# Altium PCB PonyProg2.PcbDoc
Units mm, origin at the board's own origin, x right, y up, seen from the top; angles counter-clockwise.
Board outline 221.9 x 83.4 mm, 2 copper layers (Top Layer, Bottom Layer); 90 components, 71 nets, 512 pads, 0 vias.
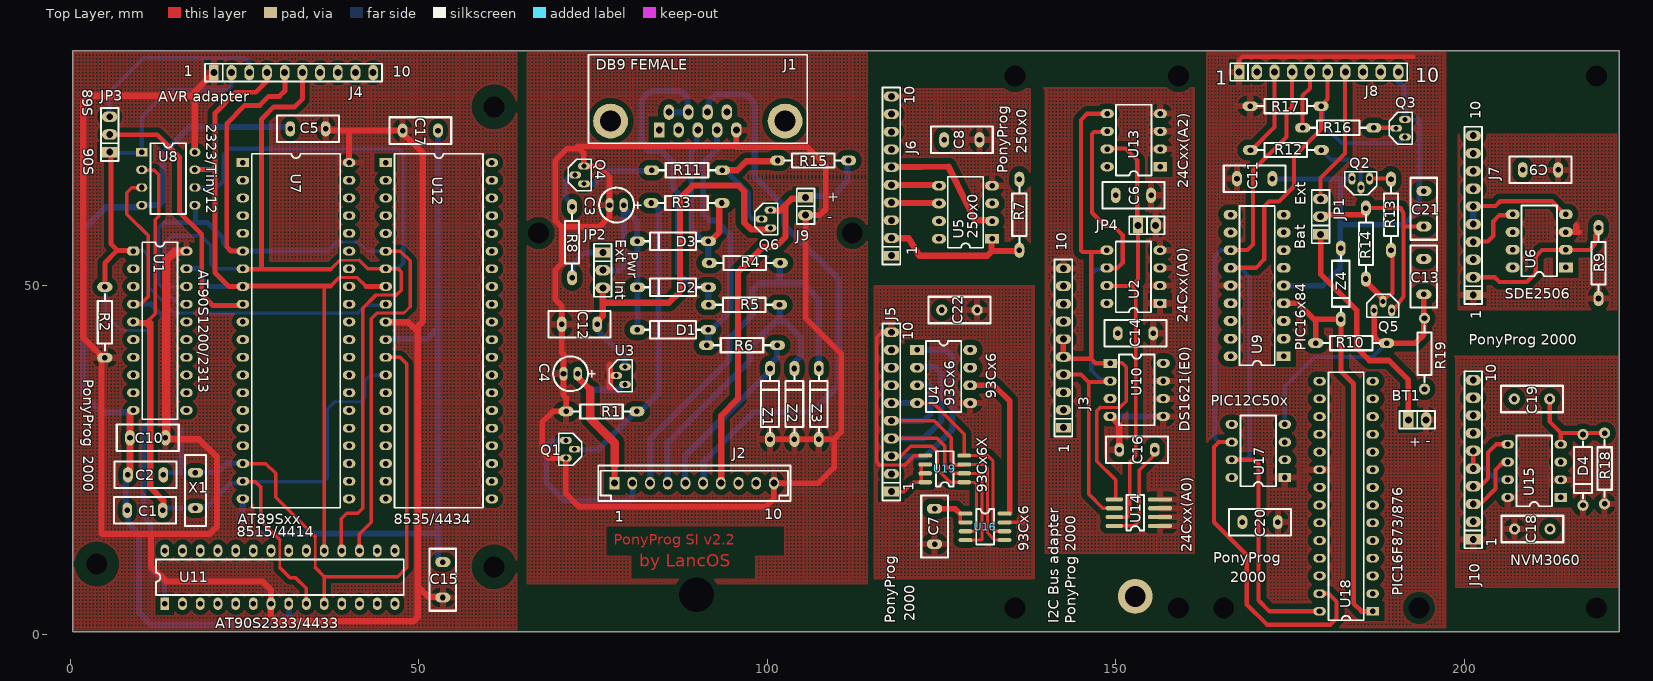
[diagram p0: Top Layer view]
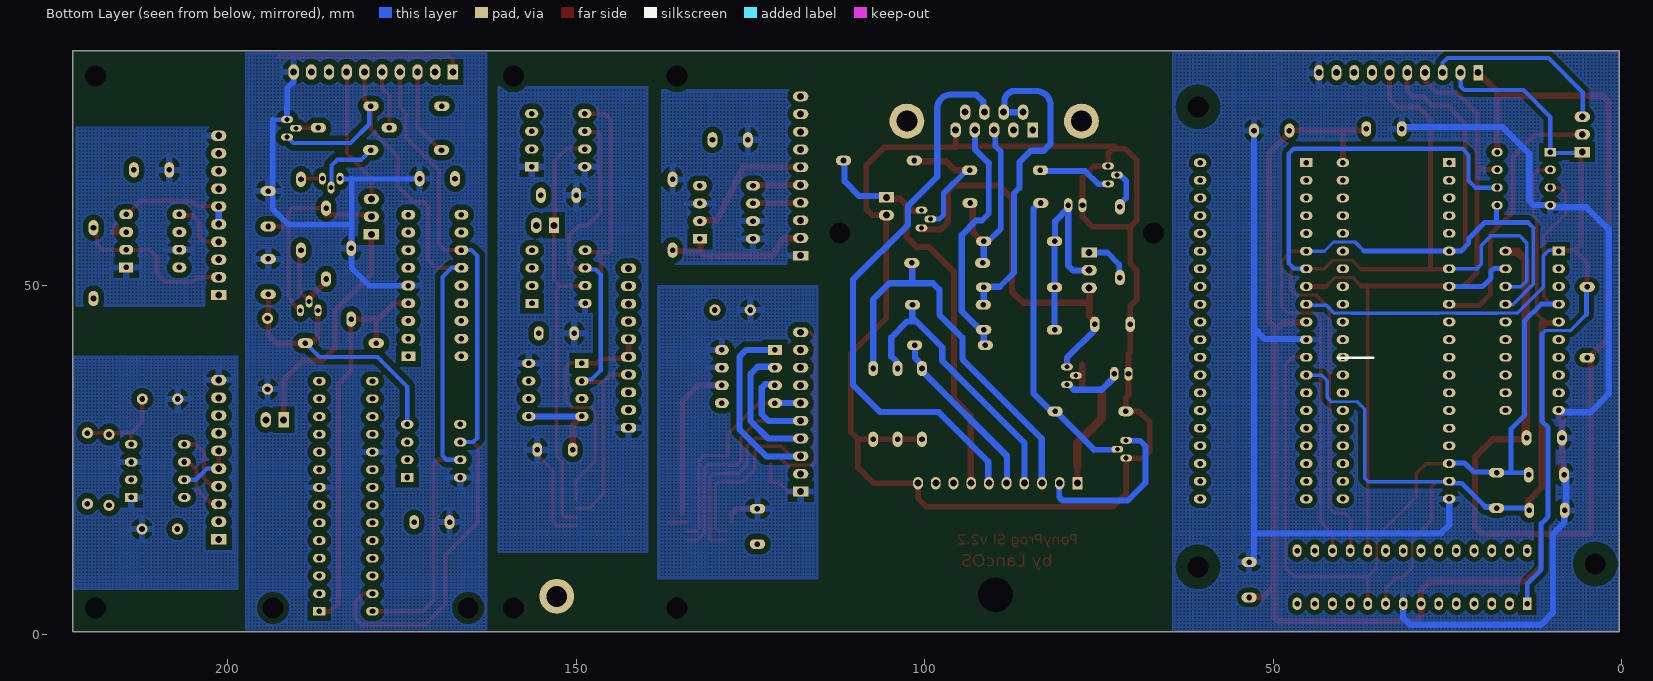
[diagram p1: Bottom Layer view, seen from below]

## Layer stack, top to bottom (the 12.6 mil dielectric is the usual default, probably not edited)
Top Solder: solder mask 0.0102, Solder Resist, Dk 3.5
Top Layer: signal copper 0.0356
Dielectric 1: dielectric 0.32, FR-4, Dk 4.8
Bottom Layer: signal copper 0.0356
Bottom Solder: solder mask 0.0102, Solder Resist, Dk 3.5

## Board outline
0.35,0.35 222.25,0.35 222.25,83.75 0.35,83.75

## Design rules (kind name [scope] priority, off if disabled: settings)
Clearance [All] p1: gap=0.35
MaximumViaCount [All] p1: limit=0
MinimumAnnularRing [All] p1: minimumring=0.125
PasteMaskExpansion PasteMaskExpansion_1 [InComponent('P1')] p1: expansion=-5.08
PasteMaskExpansion [All] p2: expansion=0
PlaneClearance [All] p1: clearance=0.254
PolygonConnect [All] p1: connectstyle=Relief reliefconductorwidth=0.889 reliefentries=4 polygonreliefangle="90 Angle" airgapwidth=0.254
RoutingLayers [All] p1: top layer_v5=TRUE bottom layer_v5=FALSE
RoutingVias [All] p1: holewidth=0.711 width=1.27 viastyle="Through Hole" minholewidth=0.711 minwidth=1.27 maxholewidth=0.711 maxwidth=1.27
SolderMaskExpansion [All] p1: expansion=0.051
Width [All] p1: maxlimit=0.889 minlimit=0.4 preferedwidth=0.4
27 further rules are at their usual default settings.

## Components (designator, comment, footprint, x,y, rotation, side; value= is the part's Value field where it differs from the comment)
BT1 "9V" SIP2 192,30.8 r0 top
C1 "27pF" RAD0.2#1 13.249,17.803 r180 top
C2 "27pF" RAD0.2#1 13.349,22.903 r180 top
C3 "47uF" CAPELET1 79.4,61.6 r0 top
C4 "47uF" CAPELET1 72.8,37.4 r0 top
C5 "100nF" RAD0.2#1 31.56,72.536 r0 top
C6 "100nF" RAD0.2#1 150,63.004 r0 top
C7 "100nF" RAD0.2#1 124.004,18.036 r270 top
C8 "100nF" RAD0.2#1 125.376,70.964 r0 top
C9 "100nF" RAD0.2#1 213.476,66.656 r180 top
C10 "100nF" RAD0.2#1 13.649,28.203 r180 top
C11 "100nF" RAD0.2#1 167.4,65.4 r0 top
C12 "100nF" RAD0.2#1 75.6,44.5 r180 top
C13 "1nF" RAD0.2#1 194.2,48.8 r90 top
C14 "100nF" RAD0.2#2 150.3,43.204 r0 top
C15 "100nF" RAD0.2#1 53.46,5.3 r90 top
C16 "100nF" RAD0.2#2 155.6,26.504 r180 top
C17 "100nF" RAD0.2#2 52.76,72.3 r180 top
C18 "100nF" MY-RAD0.2#1 207.236,15.124 r0 top
C19 "100nF" MY-RAD0.2#1 212.264,33.776 r180 top
C20 "100nF" MY-RAD0.2#2 173.264,16.116 r180 top
C21 "100nF" MY-RAD0.2#3 194.216,58.536 r90 top
C22 "100nF" MY-RAD0.2#1 125.036,46.554 r0 top
D1 "1N4148" DIODE0.4 91.537,43.71 r180 top
D2 "1N4148" DIODE0.4 91.537,49.806 r180 top
D3 "1N4148" DIODE0.4 91.537,56.41 r180 top
D4 "1N4148" MY-DIODE0.4 217.044,28.688 r270 top
J1 "DB9 FEMALE" DB9RA/F 84.503,72.388 r0 top
J2 "CON10" AMP1X10 78.1,21.7 r0 top
J3 "CON10" SIP10#1 142.5,29.664 r90 top
J4 "CON10" SIP10#2 20.6,80.6 r0 top
J5 "CON10" SIP10#2 117.8,20.5 r90 top
J6 "CON10" SIP10#2 117.8,54.34 r90 top
J7 "CON10" SIP10#3 201.3,48.7 r90 top
J8 "CON10" SIP10#3 167.7,80.7 r0 top
J9 "PLUG" SIP2 105.5,62.7 r270 top
J10 "CON10" MY-SIP10 201.3,13.636 r90 top
JP1 "JUMP3" SIP3 179.4,57.4 r90 top
JP2 "JUMP3" SIP3 76.4,54.8 r270 top
JP3 "JUMP3" SIP3 5.66,69.2 r90 top
JP4 "JUMP2" SIP2 153.2,58.704 r0 top
Q1 "BC547" TO-92A 71.1,25.3 r90 top
Q2 "BC547" TO-92A 183.9,65.4 r0 top
Q3 "BC547" TO-92A 191.5,73.9 r270 top
Q4 "BC547" TO-92A 73.7,67.2 r270 top
Q5 "BC557" TO-92A 189.6,46.5 r180 top
Q6 "BC557" TO-92A 100.47,60.87 r270 top
R1 "15K" AXIAL0.4#1 81.3,32 r180 top
R2 "10K" AXIAL0.4#2 4.96,39.7 r90 top
R3 "10K" AXIAL0.4#1 93.5,61.9 r180 top
R4 "4K7" AXIAL0.4#1 91.7,53.3 r0 top
R5 "4K7" AXIAL0.4#1 91.6,47.3 r0 top
R6 "4K7" AXIAL0.4#1 91.3,41.5 r0 top
R7 "10K" AXIAL0.4#1 136.176,55.136 r90 top
R8 "10K" AXIAL0.4#1 72,51.2 r90 top
R9 "10K" AXIAL0.4#1 219.276,58.356 r270 top
R10 "1K" AXIAL0.4#1 178.7,41.8 r0 top
R11 "4K7" AXIAL0.4#1 83.4,66.6 r0 top
R12 "2K2" AXIAL0.4#1 179.5,69.5 r180 top
R13 "4K7" AXIAL0.4#1 189.5,65.3 r270 top
R14 "10K" AXIAL0.4#1 185.9,51 r90 top
R15 "10K" AXIAL0.4#1 101.5,68 r0 top
R16 "1K" AXIAL0.4#1 187,72.7 r180 top
R17 "1K" AXIAL0.4#1 169.3,75.8 r0 top
R18 "560K" MY-AXIAL0.4 220.148,28.896 r270 top
R19 "100K" MY-AXIAL0.4 194.301,35.199 r90 top
U1 "AT90S1200/2313" DIP20 9.049,55.003 r0 top
U2 "24Cxx(A0)" DIP8#1 156.351,47.505 r180 top
U3 "LM2936Z-5" TO-92A 79.6,38.4 r270 top
U4 "93Cx6" DIP8#2 121.494,40.82 r0 top
U5 "250x0" DIP8#2 132.266,56.764 r180 top
U6 "SDE2506" DIP8#2 214.576,52.656 r180 top
U7 "AT90S4414/8515" DIP40 24.757,67.703 r0 top
U8 "AT90S2323" MY-DIP8#1 10.249,69.203 r0 top
U9 "PIC16x84" DIP18 174.1,39.9 r180 top
U10 "DS1621(E0)" DIP8#1 149.2,38.904 r0 top
U11 "AT90S2333/4433" DIP28S 13.56,4.4 r90 top
U12 "AT90S8535/4434" DIP40 45.26,67.7 r0 top
U13 "24Cxx(A2)" DIP8#1 156.4,67.104 r180 top
U14 "24Cxx(A0)" SO-8 155.6,15.564 r180 top
U15 "NVM3060" MY-DIP8#2 213.864,19.656 r180 top
U16 "93Cx6X" MY-SO-8 128.456,17.344 r0 top
U17 "PIC12C50x" MY-DIP8#2 174.264,22.516 r180 top
U18 "PIC16F873/876" MY-DIP28S 186.864,3.316 r180 top
U19 "93Cx6" MY-SO-8 128.264,21.846 r180 top
X1 "4MHz" XTAL1 17.957,23.203 r270 top
Z1 "5V1" DIODE0.4 100.4,28 r90 top
Z2 "5V1" DIODE0.4 103.9,28 r90 top
Z3 "5V1" DIODE0.4 107.4,28 r90 top
Z4 "13V" DIODE0.4 182.3,55.4 r270 top

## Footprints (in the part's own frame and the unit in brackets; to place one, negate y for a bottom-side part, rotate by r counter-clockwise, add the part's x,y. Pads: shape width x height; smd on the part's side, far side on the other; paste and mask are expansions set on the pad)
AMP1X10 [mm]
  rect 1.4x1.8 hole 1: 1(0,0)
  oval 1.4x1.8 hole 1: 2(2.54,0) 3(5.08,0) 4(7.62,0) 5(10.16,0) 6(12.7,0) 7(15.24,0) 8(17.78,0) 9(20.32,0) 10(22.86,0)
  silkscreen extent -2.35,-2.54 25.24,2.54
AXIAL0.4#1 [mm]
  oval 2.2x1.4 hole 0.8: 1(0,0) 2(10.16,0)
  silkscreen extent 1.02,-1.02 9.14,1.02
AXIAL0.4#2 [mm]
  oval 1.4x2.2 hole 0.8: 1(0,0) 2(10.16,0)
  silkscreen extent 1.02,-1.02 9.14,1.02
CAPELET1 [mm]
  oval 1.2x2 hole 0.8: 1(0,0) 2(-2.032,0)
  silkscreen extent -3.51,-2.5 2.54,2.5
DB9RA/F [mm]
  rect 1.5x2.2 hole 1: 1(0,0)
  oval 1.5x2.2 hole 1: 2(2.769,0) 3(5.537,0) 4(8.306,0) 5(11.074,0) 6(1.397,2.54) 7(4.166,2.54) 8(6.934,2.54) 9(9.703,2.54)
  round 5 hole 3: ""(-6.985,1.27) ""(18.059,1.27)
  silkscreen extent -10.16,-1.91 21.23,10.79
DIODE0.4 [mm]
  oval 2.2x1.4 hole 0.8: A(0,0) K(10.16,0)
  silkscreen extent 1.02,-1.27 9.14,1.27
DIP8#1 [mm]
  rect 1.9x1.3 hole 0.8: 1(0,0)
  oval 1.9x1.3 hole 0.8: 2(0,-2.54) 3(0,-5.08) 4(0,-7.62) 5(7.62,-7.62) 6(7.62,-5.08) 7(7.62,-2.54) 8(7.62,0)
  silkscreen extent 1.27,-8.89 6.35,1.27
DIP8#2 [mm]
  rect 2x1.4 hole 0.8: 1(0,0)
  oval 2x1.4 hole 0.8: 2(0,-2.54) 3(0,-5.08) 4(0,-7.62) 5(7.62,-7.62) 6(7.62,-5.08) 7(7.62,-2.54) 8(7.62,0)
  silkscreen extent 1.27,-8.89 6.35,1.27
DIP18 [mm]
  rect 2x1.4 hole 0.8: 1(0,0)
  oval 2x1.4 hole 0.8: 2(0,-2.54) 3(0,-5.08) 4(0,-7.62) 5(0,-10.16) 6(0,-12.7) 7(0,-15.24) 8(0,-17.78) 9(0,-20.32) 10(7.62,-20.32) 11(7.62,-17.78) 12(7.62,-15.24) 13(7.62,-12.7) 14(7.62,-10.16) 15(7.62,-7.62) 16(7.62,-5.08) 17(7.62,-2.54) 18(7.62,0)
  silkscreen extent 1.27,-21.59 6.35,1.27
DIP20 [mm]
  oct 1.8x1.25 / inner rect 1.8x1.25 / far side rect 1.8x1.25 hole 0.8: 1(0,0)
  oval 1.8x1.25 hole 0.8: 2(0,-2.54) 3(0,-5.08) 4(0,-7.62) 5(0,-10.16) 6(0,-12.7) 7(0,-15.24) 8(0,-17.78) 9(0,-20.32) 10(0,-22.86) 11(7.62,-22.86) 12(7.62,-20.32) 13(7.62,-17.78) 14(7.62,-15.24) 15(7.62,-12.7) 16(7.62,-10.16) 17(7.62,-7.62) 18(7.62,-5.08) 19(7.62,-2.54) 20(7.62,0)
  silkscreen extent 1.27,-24.13 6.35,1.27
DIP28S [mm]
  rect 1.8x1.25 hole 0.8: 1(0,0)
  oval 1.8x1.25 hole 0.8: 2(0,-2.54) 3(0,-5.08) 4(0,-7.62) 5(0,-10.16) 6(0,-12.7) 7(0,-15.24) 8(0,-17.78) 9(0,-20.32) 10(0,-22.86) 11(0,-25.4) 12(0,-27.94) 13(0,-30.48) 14(0,-33.02) 15(7.62,-33.02) 16(7.62,-30.48) 17(7.62,-27.94) 18(7.62,-25.4) 19(7.62,-22.86) 20(7.62,-20.32) 21(7.62,-17.78) 22(7.62,-15.24) 23(7.62,-12.7) 24(7.62,-10.16) 25(7.62,-7.62) 26(7.62,-5.08) 27(7.62,-2.54) 28(7.62,0)
  silkscreen extent 1.27,-34.29 6.35,1.27
DIP40 [mm]
  rect 1.8x1.25 hole 0.8: 1(0,0)
  oval 1.8x1.25 hole 0.8: 2(0,-2.54) 3(0,-5.08) 4(0,-7.62) 5(0,-10.16) 6(0,-12.7) 7(0,-15.24) 8(0,-17.78) 9(0,-20.32) 10(0,-22.86) 11(0,-25.4) 12(0,-27.94) 13(0,-30.48) 14(0,-33.02) 15(0,-35.56) 16(0,-38.1) 17(0,-40.64) 18(0,-43.18) 19(0,-45.72) 20(0,-48.26) 21(15.24,-48.26) 22(15.24,-45.72) 23(15.24,-43.18) 24(15.24,-40.64) 25(15.24,-38.1) 26(15.24,-35.56) 27(15.24,-33.02) 28(15.24,-30.48) 29(15.24,-27.94) 30(15.24,-25.4) 31(15.24,-22.86) 32(15.24,-20.32) 33(15.24,-17.78) 34(15.24,-15.24) 35(15.24,-12.7) 36(15.24,-10.16) 37(15.24,-7.62) 38(15.24,-5.08) 39(15.24,-2.54) 40(15.24,0)
  silkscreen extent 1.27,-49.53 13.97,1.27
MY-AXIAL0.4 [mm]
  round 1.6 hole 0.8: 1(0,0) 2(10.16,0)
  silkscreen extent 1.02,-1.02 9.14,1.02
MY-DIODE0.4 [mm]
  round 1.6 hole 0.8: A(0,0) K(10.16,0)
  silkscreen extent 1.02,-1.27 9.14,1.27
MY-DIP8#1 [mm]
  rect 1.6x1.2 hole 0.8: 1(0,0)
  oval 1.6x1.2 hole 0.8: 2(0,-2.54) 3(0,-5.08) 4(0,-7.62) 5(7.62,-7.62) 6(7.62,-5.08) 7(7.62,-2.54) 8(7.62,0)
  silkscreen extent 1.27,-8.89 6.35,1.27
MY-DIP8#2 [mm]
  rect 1.8x1.25 hole 0.8: 1(0,0)
  oval 1.8x1.25 hole 0.8: 2(0,-2.54) 3(0,-5.08) 4(0,-7.62) 5(7.62,-7.62) 6(7.62,-5.08) 7(7.62,-2.54) 8(7.62,0)
  silkscreen extent 1.27,-8.89 6.35,1.27
MY-DIP28S [mm]
  rect 1.8x1.25 hole 0.8: 1(0,0)
  oval 1.8x1.25 hole 0.8: 2(0,-2.54) 3(0,-5.08) 4(0,-7.62) 5(0,-10.16) 6(0,-12.7) 7(0,-15.24) 8(0,-17.78) 9(0,-20.32) 10(0,-22.86) 11(0,-25.4) 12(0,-27.94) 13(0,-30.48) 14(0,-33.02) 15(7.62,-33.02) 16(7.62,-30.48) 17(7.62,-27.94) 18(7.62,-25.4) 19(7.62,-22.86) 20(7.62,-20.32) 21(7.62,-17.78) 22(7.62,-15.24) 23(7.62,-12.7) 24(7.62,-10.16) 25(7.62,-7.62) 26(7.62,-5.08) 27(7.62,-2.54) 28(7.62,0)
  silkscreen extent 1.27,-34.29 6.35,1.27
MY-RAD0.2#1 [mm]
  round 1.6 hole 0.8: 1(0,0) 2(5.08,0)
  silkscreen extent -1.91,-1.91 6.98,1.91
MY-RAD0.2#2 [mm]
  oval 1.4x2 hole 0.8: 1(0,0) 2(5.08,0)
  silkscreen extent -1.91,-1.91 6.98,1.91
MY-RAD0.2#3 [mm]
  oval 1.4x2.2 hole 0.8: 1(0,0) 2(5.08,0)
  silkscreen extent -1.91,-1.91 6.98,1.91
MY-SIP10 [mm]
  rect 1.5x2.2 hole 1: 1(0,0)
  oval 1.5x2.2 hole 1: 2(2.54,0) 3(5.08,0) 4(7.62,0) 5(10.16,0) 6(12.7,0) 7(15.24,0) 8(17.78,0) 9(20.32,0) 10(22.86,0)
  silkscreen extent -1.27,-1.27 24.13,1.27
MY-SO-8 [mil]
  oval 78.74x24 smd: 1(0,0) 2(0,-50) 3(0,-100) 4(0,-150) 5(220,-150) 6(220,-100) 7(220,-50) 8(220,0)
  silkscreen extent 60,-175 160,25
RAD0.2#1 [mm]
  oval 1.4x2.2 hole 0.8: 1(0,0) 2(5.08,0)
  silkscreen extent -1.91,-1.91 6.98,1.9
RAD0.2#2 [mm]
  oval 1.4x2 hole 0.8: 1(0,0) 2(5.08,0)
  silkscreen extent -1.91,-1.91 6.98,1.91
SIP2 [mm]
  rect 1.5x2.2 hole 1: 1(0,0)
  oval 1.5x2.2 hole 1: 2(2.54,0)
  silkscreen extent -1.27,-1.27 3.81,1.27
SIP3 [mm]
  rect 1.5x2.2 hole 1: 1(0,0)
  oval 1.5x2.2 hole 1: 2(2.54,0) 3(5.08,0)
  silkscreen extent -1.27,-1.27 6.35,1.27
SIP10#1 [mm]
  rect 1.4x2.2 / inner rect 1.4x2.2 / far side oct 1.4x2.2 hole 1: 1(0,0)
  oval 1.4x2.2 hole 1: 2(2.54,0) 3(5.08,0) 4(7.62,0) 5(10.16,0) 6(12.7,0) 7(15.24,0) 8(17.78,0) 9(20.32,0) 10(22.86,0)
  silkscreen extent -1.27,-1.27 24.13,1.27
SIP10#2 [mm]
  rect 1.4x2.2 hole 1: 1(0,0)
  oval 1.4x2.2 hole 1: 2(2.54,0) 3(5.08,0) 4(7.62,0) 5(10.16,0) 6(12.7,0) 7(15.24,0) 8(17.78,0) 9(20.32,0) 10(22.86,0)
  silkscreen extent -1.27,-1.27 24.13,1.27
SIP10#3 [mm]
  rect 1.5x2.2 hole 1: 1(0,0)
  oval 1.5x2.2 hole 1: 2(2.54,0) 3(5.08,0) 4(7.62,0) 5(10.16,0) 6(12.7,0) 7(15.24,0) 8(17.78,0) 9(20.32,0) 10(22.86,0)
  silkscreen extent -1.27,-1.27 24.13,1.27
SO-8 [mm]
  oval 3.5x0.61 smd: 1(-0.75,0) 2(-0.75,-1.27) 3(-0.75,-2.54) 4(-0.75,-3.81)
  oval 2.5x0.61 smd: 5(5.8,-3.81) 6(5.8,-2.54) 7(5.8,-1.27) 8(5.8,0)
  silkscreen extent 1.52,-4.44 4.06,0.64
TO-92A [mm]
  oval 1x1.7 hole 0.7: 1(0,0) 2(1.27,-1.27) 3(2.54,0)
  silkscreen extent -1.02,-2.29 3.56,1.02
XTAL1 [mm]
  oval 1.4x2.2 hole 0.8: 1(0,0) 2(5.08,0)
  silkscreen extent -2.54,-1.52 7.62,1.52

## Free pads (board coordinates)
  round 1 hole 3: ""(3.8,10.1) ""(60.8,9.7) ""(60.8,75.7) ""(67.2,57.6) ""(112.2,57.6) ""(135.57,3.8) ""(135.57,80.1) ""(159,3.8) ""(159,80.1) ""(165.5,3.8) ""(193.5,3.8) ""(219,3.8) ""(219,80.1)
  round 1 hole 5: ""(89.85,5.7)
  round 5 hole 3: ""(152.8,5.464)

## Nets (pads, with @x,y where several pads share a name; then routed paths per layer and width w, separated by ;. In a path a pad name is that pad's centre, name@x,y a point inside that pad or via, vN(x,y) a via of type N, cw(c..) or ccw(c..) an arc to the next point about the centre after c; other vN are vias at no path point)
GND: C3.2 C4.2 C12.2 J1.5 J2.10 J9.2 Q1.1 Q4.1 R1.2 U3.2 Z1.A Z2.A Z3.A | length 221.9
  Top Layer w0.8: 70.4,58.496 75.916,58.496 77.368,59.948 77.368,65.564 75.732,67.2 73.664,67.2 73.664,69.1 ; 70.5,58.488 69.6,59.388 69.6,68.048 71.224,69.672 73.076,69.672 ; 70.5,58.496 70.5,53.2 69.6,52.3 69.6,48.016 70.52,47.096 C12.2@70.52,44.7 ; C12.2 70.52,40.488 70.768,40.24 C4.2@70.768,37.7 ; C4.2@70.768,36.9 70.768,34.356 71.14,33.984 R1.2 ; R1.2@70.9,32 69.244,32 67.7,30.456 67.7,26.284 68.684,25.3 Q1.1@71.047,25.3 ; Q1.1@71.1,25.261 71.1,20.224 73.024,18.3 99.772,18.3 100.96,19.488 J2.10 107.34,21.7 109.584,23.944 109.584,28 ; 73,69.672 73.357,70.029 ; 73.664,69.084 72.719,70.029 95.987,70.029 ; J1.5@95.577,72.2 95.577,69.9 105.8,69.9 108.4,67.3 108.4,61 107.56,60.16 J9.2@105.8,60.16 ; Z1.A Z3.A@107.1,28 ; J9.2 105.5,45.408 110.6,40.308 110.6,29.016 109.584,28 ; Z3.A@107.6,28 109.584,28
  Top Layer w0.889: 77.4,35.48 77.4,38.684 ; 77.4,37.13 U3.2
N00001: C6.1 C14.1 C16.1 J3.1 U2.8 U10.8 U13.1 U13.8 U14.8 | length 14.2
  Top Layer w0.5: U14.8@150.012,15.564 152.66,15.564 ; 152.7,15.564 153.4,16.264 153.4,23.564 C16.1@155.7,25.864
N00002: C6.2 C14.2 C16.2 J3.10 JP4.2 U2.1 U2.2 U2.3 U2.4 U10.4 U10.5 U10.6 U10.7 U13.2 U13.3 U13.4 U14.1 U14.2 U14.3 U14.4 | length 12.4
  Top Layer w0.889: U10.4@149.345,31.22 150.52,30.044 C16.2
  Bottom Layer w0.889: U10.4@149.62,31.284 U10.5
N00004: C9.2 J7.10 U6.1 U6.7
N00006: J7.4 U6.5 | length 7
  Top Layer w0.6: J7.4@202.076,56.356 203.376,56.356 204.176,57.156 204.176,59.256 205.076,60.156 U6.5@206.276,60.156
N00007: J2.7 J9.1 Q6.1 R15.2 | length 56.9
  Top Layer w0.889: J2.7@93.4,22.4 93.4,31.4 95.8,33.8 95.8,52 99.4,55.6 101.2,55.6 102.609,57.009 102.609,61.609
  Top Layer w0.9: 101.372,60.8 101.8,60.8 103.5,62.5 J9.1@104.6,62.5
  Bottom Layer w0.889: J9.1@106.1,62.9 109.4,62.9 111.5,65 R15.2@111.5,67.6
N00008: Q4.3 R11.1 | length 9.2
  Bottom Layer w0.8: Q4.3@74.1,64.6 75.1,64.6 77,66.5
  Bottom Layer w0.889: 77,66.5 R11.1@82.5,66.5
N00009: Q6.2 R11.2 R15.1 | length 16.2
  Top Layer w0.889: R11.2@94,66.6 95.7,66.6 97,67.9 R15.1@100.5,67.9
  Bottom Layer w0.7: 97.3,63.3 97.3,60.2 97.9,59.6 Q6.2@98.9,59.6
  Bottom Layer w0.8: R11.2@94.3,66.3 97.3,63.3
N00011: D2.A J1.6 J1.7 R5.1 | length 45.8
  Bottom Layer w0.8: 86.4,64.1 87.2,63.3 87.2,51.9 89.2,49.9
  Bottom Layer w0.889: 86.4,64.1 86.4,67.8 84.8,69.4 82.919,69.4 81.963,70.356 81.963,75.944 cw(c83.995,75.944) 83.995,77.976 87.043,77.976 cw(c87.043,76.452) 88.567,76.452 J1.7@88.567,75.436 ; J1.6@86.528,74.928 J1.7 ; 89.2,49.9 D2.A@90.9,49.9 ; R5.1@91.537,47.663 D2.A
N00013: D3.A J1.3 R3.1 R4.1 | length 24.5
  Top Layer w0.889: D3.A@92.1,56.7 93.1,57.7 R3.1@93.1,61.5
  Bottom Layer w0.8: J1.3@89.9,71.8 89.9,70.1 89.1,69.3 89.1,58.2 D3.A@90.8,56.5
  Bottom Layer w0.889: R4.1@91.537,53.463 D3.A
N00014: J1.8 J2.6 | length 80.5
  Bottom Layer w0.889: J2.6@90.9,22.1 90.9,24.8 98,31.9 106.4,31.9 110.3,35.8 110.3,50.9 102.4,58.8 102.4,61.5 98.219,65.681 98.219,75.436 ccw(c96.187,75.436) 96.187,77.468 92.631,77.468 91.615,76.452 J1.8@91.615,75.436
N00015: D1.A J1.4 R6.1 | length 33.9
  Bottom Layer w0.8: 90.8,67.6 90.8,60.4 91.8,59.4
  Bottom Layer w0.889: 90.8,67.6 92.8,69.6 J1.4@92.8,71.8 ; R6.1@91.537,41.837 D1.A ; 91.8,59.4 92.6,59.4 94.7,57.3 94.7,46.4 D1.A@92.1,43.8
N00017: C12.1 JP2.3 Q6.3 U3.1 | length 55.8
  Top Layer w0.889: C12.1@75.8,45.1 76.4,45.7 JP2.3 ; 76.4,47.6 85.9,47.6 87.5,49.2 87.5,62.6 89.3,64.4 95.9,64.4 96.7,63.6 96.7,59.1 97.7,58.1
  Top Layer w0.9: 97.7,58.1 Q6.3@100.5,58.1
  Bottom Layer w0.889: C12.1@75.7,43.6 79.6,39.7 U3.1
N00018: Q4.2 R8.2 | length 4.5
  Bottom Layer w0.8: R8.2@71.8,61.9 71.1,62.6 71.1,65.1 Q4.2@71.8,65.8
N00019: J7.2 R9.1 U6.2 | length 21.1
  Top Layer w0.6: J7.2@202.076,51.256 204.376,51.256 205.076,50.556 208.976,50.556 210.276,51.856 210.276,54.256 211.176,55.156 U6.2@213.876,55.156 ; U6.2@215.376,55.156 217.952,55.156 218.776,55.98 218.776,57.256 R9.1@219.276,57.756
N00020: C9.1 J7.1 R9.2 U6.3 | length 1.7
  Top Layer w0.889: U6.3@215.276,57.756 216.449,57.756 ; 216.076,58.056 216.076,58.627
N00021: J7.5 J7.6 U6.4 | length 15.4
  Top Layer w0.6: J7.6@201.976,61.456 204.476,61.456 205.176,62.156 212.576,62.156 U6.4@214.176,60.556
  Bottom Layer w0.889: J7.5 J7.6@201.3,61.156
N00022: JP2.1 R8.1 | length 5.3
  Bottom Layer w0.8: R8.1@72.1,51.9 72.1,53.1 73.8,54.8 JP2.1@75.5,54.8
N00023: JP4.1 U2.7 U13.7 U14.7 | length 60
  Top Layer w0.5: U14.7@150.012,16.834 151.67,16.834 152,17.164 152,24.764 152.9,25.664 152.9,49.404 152.3,50.004
  Top Layer w0.6: U2.7@149.3,50.004 152.3,50.004 153.2,50.904 JP4.1@153.2,58.004 ; U13.7@149.3,69.704 151.4,69.704 153.1,68.004 JP4.1@153.1,59.504
N00024: J3.4 U2.6 U10.2 U13.6 U14.6 | length 69.7
  Top Layer w0.5: 146.1,36.204 146.1,20.164 148.16,18.104 U14.6@150.012,18.104
  Top Layer w0.6: J3.4@143.16,37.304 145,37.304 146.1,36.204 U10.2@148.5,36.204 ; U13.6@148,72.104 146.9,72.104 146.6,71.804 146.6,60.504 148.5,58.604 149.7,58.604 151,57.304 151,53.304 150.2,52.504 U2.6@149.1,52.504
  Bottom Layer w0.6: U2.6@148.2,52.364 147.2,52.364 146.5,51.664 146.5,37.864 147.8,36.564 U10.2@148.5,36.564
N00025: J3.5 J3.6 U2.5 U10.1 U13.5 U14.5 | length 73.7
  Top Layer w0.4: 147.8,32.564 150.6,32.564
  Top Layer w0.5: 147.8,32.564 147.3,32.064 147.3,24.864 150.012,22.152 U14.5@150.012,19.374 ; U10.1@149.8,38.964 150.9,38.964 151.5,38.364 151.5,33.464 150.6,32.564
  Top Layer w0.6: J3.5@143.4,39.564 146.5,39.564 ; 146.5,54.504 146.5,39.504 147.1,38.904 U10.1@148.6,38.904 ; U13.5@148,74.704 145.9,74.704 145,73.804 145,55.104 145.24,54.864 U2.5@148.1,54.864
  Top Layer w0.8: J3.5 J3.6
N00026: J2.3 R4.2 Z3.K | length 55.7
  Bottom Layer w0.889: J2.3@83.2,22.4 83.2,28.1 94.6,39.5 94.6,42.6 97.9,45.9 97.9,49.48 98.82,50.4 105.1,50.4 107.4,48.1 Z3.K@107.4,38.9 ; 101.8,50.4 R4.2@101.8,52.9
N00027: J2.4 R5.2 Z2.K | length 39.7
  Bottom Layer w0.889: J2.4@85.7,22.3 85.7,27.5 97.5,39.3 97.5,41.2 101.8,45.5 R5.2@101.8,46.8 ; 101.203,44.903 102.497,44.903 104.8,42.6 104.8,39.9 Z2.K@103.9,39
N00028: J2.5 R6.2 Z1.K | length 22.6
  Bottom Layer w0.889: J2.5@88.2,22.3 88.2,25.6 Z1.K@100.1,37.5 ; Z1.K@100.5,38.8 101.4,39.7 R6.2@101.4,40.9
N00029: C3.1 D1.K D2.K D3.K JP2.2 | length 27.7
  Bottom Layer w0.864: D1.K D2.K@81.377,49.524 ; D2.K D3.K@81.377,56.128
  Bottom Layer w0.889: JP2.2@77.1,52.2 78.7,52.2 79.4,52.9 C3.1@79.4,60.8 ; C3.1@79.4,61.2 81.3,59.3 D3.K@81.3,56.9
N00031: Q1.2 R1.1 R3.2 | length 40.9
  Bottom Layer w0.8: Q1.2@72.9,26.5 75.7,26.5
  Bottom Layer w0.889: 75.7,26.5 R1.1@80.8,31.6 ; R1.1@82,32.2 84.4,34.6 84.4,61.1 R3.2@83.7,61.8
N00041: J2.2 Q1.3 | length 22.5
  Bottom Layer w0.8: 68.3,27 69.1,27.8 Q1.3@70.4,27.8
  Bottom Layer w0.85: 68.3,27 68.3,21.8 70.9,19.2 80.2,19.2 80.7,19.7 J2.2@80.7,20.9
N00046: C7.1 C22.1 J5.1 U4.6 U4.7 U4.8 U16.1 U16.2 U16.8 U19.6 U19.7 U19.8 | length 35.4
  Top Layer w0.5: J5.1 119.6,20.5 120.946,21.846 122.1,21.846 U19.6@122.1,24.4 ; U16.2@127.7,16 U16.1@127.7,17.3
  Top Layer w0.8: C7.1 126.964,18.036 U16.1@127.7,17.3 ; U4.6 132.56,35.74 134.8,33.5 U16.8@134.8,17.4
N00047: C7.2 C22.2 J5.10 U4.5 U16.7 U19.5 | length 30.8
  Top Layer w0.4: 116.1,24.3 119.7,24.3
  Top Layer w0.5: 116.1,24.3 115.7,24.7 115.7,42.6 116.46,43.36 J5.10 ; 119.7,24.3 121.056,25.656 U19.5 ; U16.7 136.826,16.074
N00048: J5.3 U4.1 U16.3 U19.1 | length 50.5
  Top Layer w0.4: U19.1 129.654,21.846 130.025,21.475 130.025,15.225 129.604,14.804 U16.3
  Top Layer w0.5: J5.3@117.3,25.58 119.16,25.58 120.58,27 123.6,27 124.4,26.2 124.4,23.7 126.254,21.846 U19.1
  Bottom Layer w0.889: J5.3@118.194,25.52 122.694,25.52 126.594,29.42 126.594,39.82 125.594,40.82 U4.1@121.994,40.82
N00049: J5.4 U4.2 U16.4 U19.2 | length 47.1
  Top Layer w0.45: U19.2 130.384,23.116 130.8,22.7 130.8,13.534 U16.4 ; 130.634,13.534 130.8,13.7
  Top Layer w0.5: J5.4@117.3,28.12 124.38,28.12 125.5,27 125.5,24.3 126.684,23.116 U19.2
  Bottom Layer w0.889: J5.4@118.194,28.12 122.494,28.12 124.994,30.62 124.994,37.42 123.994,38.42 U4.2@121.994,38.42
N00050: C19.1 D4.A R18.1 U15.4 | length 13.5
  Top Layer w0.6: C19.1 212.264,30.536 213.904,28.896 R18.1 ; U15.4 213.864,28.936
N00051: C18.1 D4.K J10.1 R18.2 U15.2 U15.8
N00052: C18.2 C19.2 J10.10 U15.1 U15.3
N00053: J6.2 R7.1 U5.1 | length 21.2
  Top Layer w0.889: J6.2@117.678,56.851 120.302,56.832 121.802,54.332 131.572,54.332 132.276,55.036 R7.1@135.876,55.036 ; 132.176,55.136 U5.1@132.176,56.436
N00054: J6.6 U5.2 | length 18
  Top Layer w0.889: J6.6@118.502,67.032 126.002,67.132 129.802,59.432 U5.2@131.702,59.432
N00055: C8.1 J6.1 R7.2 U5.3 U5.7 U5.8
N00056: C8.2 J6.10 U5.4
N00057: J5.5 U4.3 U16.5 U19.3 | length 42.2
  Top Layer w0.45: U19.3 131.114,24.386 131.6,23.9 131.6,14.6 132.666,13.534 U16.5
  Top Layer w0.5: J5.5@117.3,30.66 123.94,30.66 126.4,28.2 126.4,24.9 126.914,24.386 ; 127,24.3 U19.3@128.1,24.3
  Bottom Layer w0.889: J5.5@118.194,30.62 122.394,30.62 123.394,31.62 123.394,35.42 122.894,35.92 U4.3@121.794,35.92
N00058: J5.6 U4.4 U16.6 U19.4 | length 31.5
  Top Layer w0.45: U19.4 131.644,25.656 132.4,24.9 132.4,15.2 132.796,14.804 U16.6
  Top Layer w0.5: U4.4 123.8,33.2 128.264,28.736 U19.4
  Bottom Layer w0.889: J5.6@117.302,33.2 U4.4@121.174,33.2
N00063: J10.4 U15.5 | length 9.6
  Top Layer w0.6: J10.4 202.256,21.256 203.4,22.4 203.4,26.1 204.576,27.276 U15.5
N00064: J10.3 U15.6 | length 8.4
  Top Layer w0.6: J10.3 202.316,18.716 204.5,20.9 204.5,23.6 U15.6@205.6,24.7
N00065: J10.5 J10.6 U15.7 | length 8.1
  Top Layer w0.6: J10.5 J10.6
  Bottom Layer w0.6: J10.5 203.004,23.796 204.604,22.196 U15.7
N00066: J6.4 U5.6 | length 6.4
  Top Layer w0.864: J6.4@117.678,61.931 U5.6@124.051,61.931
N00067: J6.5 U5.5 | length 6.4
  Top Layer w0.864: J6.5@117.678,64.471 U5.5@124.051,64.471
N00076: C11.2 C13.2 C20.2 C21.2 J8.10 Q2.1 Q3.1 R19.1 U9.5 U17.8 U18.8 U18.19 Z4.A | length 66.6
  Bottom Layer w0.7: 182.4,65.356 Q2.1@183.64,65.356 ; Q3.1@192.14,73.856 193.572,73.856
  Bottom Layer w0.8: C11.2@172.524,65.356 182.15,65.312 ; U9.5 179.76,50.06 182.2,52.5 182.2,65.356 ; 182.2,58.8 191.3,58.8 193.572,61.072 193.572,73.856 ; J8.10 190.56,79.34 191.5,78.4 191.5,75.768
  Bottom Layer w0.889: Q3.1 191.5,75.768
N00077: C13.1 Q5.3 R10.2 R19.2 U17.4 | length 38.9
  Top Layer w0.8: 187.1,42.6 Q5.3@187.1,46.4 ; 187.2,42.6 R10.2@187.8,42 ; R10.2 193,41.8 194.2,43 C13.1
  Bottom Layer w0.6: U17.4 174.264,35.564 178.5,39.8 186.86,39.8 R10.2
N00079: C1.2 C2.2 C5.1 C10.2 C15.2 C17.1 J4.10 U1.10 U7.20 U8.4 U11.8 U12.11 | length 222
  Top Layer w1: C2.2@8.56,23.5 C10.2@8.56,27.5 ; C10.2 U1.10@8.569,31.891
  Bottom Layer w0.889: C1.2@7.96,18.1 C2.2@7.96,22.6 ; C1.2@8.26,17.1 8.26,16 9.86,14.4 9.86,3.1 11.56,1.4 30.36,1.4 31.36,2.4 U11.8@31.36,3.7 ; U1.10@8.569,31.891 4.469,31.891 1.86,34.5 1.86,58.1 5.06,61.3 U8.4@9.76,61.3 ; U8.4@10.86,61.6 12.66,61.6 13.26,62.2 13.26,69 17.06,72.8 C5.1@31.26,72.8 ; U7.20 24.757,15.697 25.954,14.5 52.76,14.5 ; U12.11@45.86,42.4 51.26,42.4 52.76,43.9 ; C15.2@52.76,10.5 C17.1
N00080: R10.1 U9.4 U18.1 Z4.K | length 57.7
  Top Layer w0.7: Z4.K 182.3,37.8 184.1,36 184.1,4.5 185.284,3.316 U18.1
  Top Layer w0.8: U9.4 176.18,47.52 178.7,45 ; 178.46,45.24 Z4.K ; R10.1 178.7,45.24
N00101: J4.2 JP3.1 R2.2 U1.1 U8.1 U11.1 U12.9 | length 138.7
  Top Layer w0.7: R2.2 4.96,53.3 6.76,55.1 ; JP3.1@5.86,69 5.86,56 6.76,55.1 ; U1.1@8.36,55.1 6.76,55.1
  Bottom Layer w0.4: 7.36,43.6 10.96,43.6 ; 14.96,46.1 17.96,46.1 ; 23.86,46.1 26.26,46.1 ; 38.66,46.1 41.26,46.1
  Bottom Layer w0.5: 5.06,45.9 7.36,43.6 ; U1.1@9.76,55.1 10.46,55.1 11.26,54.3 11.26,49.8 14.96,46.1 ; 10.96,43.6 11.46,43.1 ; 17.96,46.1 23.86,46.1 ; 26.26,46.1 38.66,46.1 ; 41.26,46.1 42.36,47.2 U12.9@44.66,47.2
  Bottom Layer w0.6: JP3.1@6.56,69.1 U8.1@9.66,69.1 ; U8.1 10.249,74.249 14.1,78.1 22.6,78.1 23.1,78.6 J4.2@23.1,80
  Bottom Layer w0.7: 5.06,45.9 R2.2@5.06,49.5 ; 11.46,43.1 11.46,30.6 10.56,29.7 10.56,16.9 11.56,15.9 11.56,9.3 13.56,7.3 U11.1@13.56,5
N00103: Q2.3 R13.1 | length 3.1
  Top Layer w0.6: Q2.3 R13.1@189.5,65.4
N00104: Q5.2 R13.2 R14.1 | length 10.7
  Top Layer w0.6: Q5.2@188.36,48.14 189.7,48.94 R13.2@189.7,54.6
  Top Layer w0.8: R14.1@185.9,50.6 Q5.2@188.33,48.17
N00112: C21.1 JP1.2 Q5.1 R14.2 | length 29.5
  Top Layer w0.6: R14.2 190.9,61.2 191.3,60.4 191.3,48.5 Q5.1@189.9,46.5 ; 191.436,58.536 C21.1
  Top Layer w0.8: JP1.2@179.5,60.24 R14.2@185.94,60.24
N00113: Q2.2 R12.1 | length 8.6
  Bottom Layer w0.6: R12.1@179.9,69.1 180.9,68.1 184.3,68.1 185.1,67.3 Q2.2@185.1,64.6
N00132: J8.3 R12.2 | length 12.1
  Top Layer w0.6: R12.2@169.8,69.8 172.78,72.78 J8.3
N00133: C5.2 C10.1 C15.1 C17.2 J4.1 R2.1 U1.20 U7.40 U8.8 U11.7 U12.10 | length 296.6
  Top Layer w0.889: 2.739,77.279 17.59,77.279 ; 2.86,77.4 1.86,76.4 1.86,42.6 4.46,40 4.46,14.5 4.56,14.4 19.96,14.4 21.06,15.5 21.06,25.4 18.46,28 C10.1@13.76,28 ; 11.56,14.4 11.56,9.8 13.76,7.6 27.56,7.6 28.8,6.36 U11.7 ; U8.8 17.869,77.869 J4.1 ; U11.7@28.76,3.7 28.76,2.7 29.56,1.9 49.26,1.9 49.86,2.5 49.86,44.2 50.56,44.9 50.56,69.1 C17.2@47.86,71.8 ; C5.2@36.876,72.3 C17.2 ; U7.40 39.997,72.163 ; U12.10@45.86,44.8 48.46,44.8 49.86,43.4 ; 49.86,6.9 51.36,5.4 C15.1@52.66,5.4
  Top Layer w1.2: C10.1@13.76,28.7 13.76,53.7 14.96,54.9 U1.20@15.86,54.9
N00134: BT1.1 JP1.1 | length 33.5
  Top Layer w0.8: JP1.1 179.4,51.7 184.6,46.5 184.6,41.1 186.4,39.3 189.2,39.3 192,36.5 BT1.1
N00135: J8.7 JP1.3 | length 18.7
  Top Layer w0.6: JP1.3@179.4,62.7 179.4,65.5 182.9,69 J8.7@182.9,80
N00144: J4.5 U1.17 U7.6 U8.5 U11.17 U12.6 | length 130.4
  Top Layer w0.4: 43.96,46.1 47.86,46.1 48.76,47
  Top Layer w0.5: U11.17@41.46,12.6 41.46,14.4 43.16,16.1 43.16,45.3 43.96,46.1 ; U12.6@45.96,55 47.36,55 48.76,53.6 48.76,47
  Top Layer w0.7: U7.6@23.957,55.003 23.057,55.003 22.449,55.611 22.449,73.303 25.046,75.9 27.2,75.9 28.5,77.2 30,77.2 30.8,78 J4.5@30.8,80.1
  Bottom Layer w0.4: 38.26,56.3 41.36,56.3 42.66,55
  Bottom Layer w0.5: 12.66,58.314 12.66,50.3 15.66,47.3 U1.17@15.86,47.3 ; 36.96,55 38.26,56.3 ; 42.66,55 U12.6
  Bottom Layer w0.6: 12.66,58.314 13.449,59.103
  Bottom Layer w0.7: 13.449,59.103 19.649,59.103 21.949,56.803 21.949,56.111 23.057,55.003 U7.6@23.957,55.003 ; 17.949,59.403 U8.5@17.949,61.003 ; U7.6@25.26,55 36.96,55
N00145: J4.6 U1.18 U7.7 U8.6 U11.18 U12.7 | length 175
  Top Layer w0.4: 38.66,53.7 41.46,53.7 ; 43.86,48.7 46.76,48.7
  Top Layer w0.5: 37.36,52.4 38.66,53.7 ; U11.18@38.86,12.5 38.86,16.6 39.66,17.4 41.26,17.4 41.96,18.1 41.96,46.8 43.86,48.7 ; 41.46,53.7 42.7,52.46 U12.7 ; U12.7@45.96,52.5 46.96,52.5 47.46,52 47.46,49.4 46.76,48.7
  Top Layer w0.7: U7.7@25.16,52.4 37.36,52.4 ; 27.46,52.4 27.46,73.96 29.2,75.7 32.2,75.7 33.3,76.8 J4.6@33.3,80
  Bottom Layer w0.5: U1.18@15.957,49.903 14.457,49.903 13.657,50.703 13.657,56.211 14.649,57.203 18.749,57.203 20.149,55.803 20.149,53.111 20.757,52.503 U7.7@24.057,52.503
  Bottom Layer w0.6: U8.6@18.46,64.1 20.96,64.1 21.96,65.1 21.96,68.8 22.86,69.7 47.06,69.7 47.76,69 47.76,53.2 47.06,52.5 U12.7@45.76,52.5
N00146: J4.4 U1.19 U7.8 U8.7 U11.19 U12.8 | length 107.3
  Top Layer w0.4: 38.56,51.2 41.16,51.2
  Top Layer w0.5: U11.19 36.42,49.96 ; 37.36,50 38.56,51.2 ; 41.16,51.2 42.44,49.92
  Top Layer w0.7: U8.7@18.249,66.703 20.757,66.703 ; U7.8@24.257,49.923 22.737,49.923 20.757,51.903 20.757,74.803 23.754,77.8 26.6,77.8 28.3,79.5 J4.4@28.3,80 ; U7.8@25.26,50 37.36,50 ; 42.44,49.92 U12.8
  Bottom Layer w0.7: U1.19@17.249,52.503 18.349,52.503 18.749,52.103 18.749,51.122 19.948,49.923 U7.8@24.257,49.923
N00153: J8.4 U9.12 U17.6 U18.27 | length 108.5
  Top Layer w0.6: U9.12 168.9,55.14 169.7,55.94 169.7,66.6 174.5,71.4 174.5,74.9 175.3,75.7 J8.4@175.3,80 ; U17.6 164.796,27.596 164.1,26.9 164.1,16.1 168.8,11.4 168.8,4.3 171.7,1.4 180.8,1.4 181.7,2.3 181.7,4.7 180.544,5.856 U18.27
  Bottom Layer w0.6: U9.12 165.04,55.14 164.2,54.3 164.2,28.193 164.796,27.596 U17.6
N00154: J8.6 Q3.3 R17.2 U9.13 U17.7 U18.28 | length 116.1
  Top Layer w0.6: U9.13 170.1,52.6 171.3,53.8 171.3,61.4 172,62.1 173.4,62.1 175.6,64.3 175.6,68.6 179.5,72.5 R17.2@179.5,75.5 ; U17.7 169.844,25.056 170.5,24.4 ; 170.5,24.5 170.5,4.9 172.084,3.316 U18.28 ; R17.2@179.8,76.2 180.4,76.8 J8.6
  Bottom Layer w0.6: U9.13 167.9,52.6 169.2,51.3 169.2,25.656 168.6,25.056 U17.7 ; R17.2@179.7,75.6 179.7,73.2 182.4,70.5 190.6,70.5 Q3.3@191.2,71.1
N00155: BT1.2 C11.1 C20.1 J8.1 R17.1 U9.14 U17.1 U18.20 | length 26.9
  Top Layer w0.6: J8.1 167.7,82.4 168.2,82.9 192.7,82.9
N00176: J4.3 JP3.3 | length 26.3
  Bottom Layer w0.6: JP3.3@5.6,74.6 5.6,77.8 10.5,82.7 25,82.7 25.7,82 J4.3@25.7,81.3
N00177: JP3.2 U7.9 | length 37.5
  Top Layer w0.7: JP3.2@6.36,71.7 12.46,71.7 15.66,68.5 15.66,60.6 18.86,57.4 18.86,48.8 20.46,47.2 U7.9@24.06,47.2
N00201: Q3.2 R16.1 | length 3.2
  Top Layer w0.6: R16.1 Q3.2@190.16,72.7
N00202: J8.5 R16.2 | length 8
  Top Layer w0.6: R16.2@176.8,73.1 176.8,77.3 177.86,78.36 J8.5
VCC: C4.1 J2.1 U3.3 | length 23.7
  Top Layer w0.88: J2.1@78.1,22.1 78.1,24.2
  Top Layer w0.95: C4.1@73,36.7 74.6,35.1
  Top Layer w1.2: 74.6,35.1 74.6,31 78.1,27.5 78.1,24.2
  Bottom Layer w0.889: 78.6,35.1 U3.3@79.1,35.6
  Bottom Layer w0.95: C4.1@73,36.7 74.6,35.1 78.6,35.1
XTAL1_1: C1.1 U1.5 U7.19 U8.2 U11.9 U12.13 X1.2 | length 119.8
  Top Layer w0.4: 30.06,9.6 30.06,13.6
  Top Layer w0.5: U8.2@10.6,66.6 12.037,66.6 12.704,65.933 12.704,60.012 12.2,59.508 12.2,46.04 10.86,44.7 ; U7.19@25.16,21.9 26.56,21.9 27.36,21.1 27.36,16.3 30.06,13.6 ; 30.06,9.6 31.56,8.1 32.36,8.1 33.86,6.6 U11.9@33.86,5.1
  Top Layer w0.889: U1.5@9.76,44.7 11.46,44.7 11.46,21.1 13.36,19.2 C1.1@13.36,18.6 ; 10.86,44.7 11.46,44.1
  Bottom Layer w0.4: 37.96,33.4 41.66,33.4
  Bottom Layer w0.5: U7.19@25.16,21.9 36.36,21.9 36.86,22.4 36.86,32.3 37.96,33.4 ; 41.66,33.4 42.26,34 42.26,36.4 43.06,37.2 U12.13@44.76,37.2
  Bottom Layer w0.7: C1.1@13.583,18.123 X1.2 ; 19.56,18.3 22.96,21.7 U7.19@24.26,21.7
  Bottom Layer w0.889: X1.2@18.86,18.3 19.56,18.3
XTAL2_1: C2.1 U1.4 U7.18 U8.3 U11.10 U12.12 X1.1 | length 129.1
  Top Layer w0.4: 35.16,9.6 35.16,14
  Top Layer w0.5: U1.4 10.083,47.383 11.18,48.48 11.18,57.232 8.1,60.312 8.1,63.4 8.8,64.1 U8.3@9.8,64.1 ; U7.18@25.46,24.5 28.06,24.5 29.46,23.1 29.46,19.7 35.16,14 ; 35.16,9.6 36.46,8.3 ; U11.10@36.46,5 36.46,8.3 ; U12.12@45.86,39.8 47.26,39.8 48.26,38.8 48.26,9.6 46.96,8.3 36.46,8.3
  Bottom Layer w0.7: U1.4@9.66,47.4 11.56,47.4 13.96,45 13.96,31.4 15.86,29.5 15.86,23.203 ; C2.1@13.857,23.203 X1.1 ; X1.1@18.357,23.303 21.257,23.303 22.557,24.603 U7.18@24.257,24.603
pads on no net: J1. J1.1 J1.2 J1.9 J2.8 J2.9 J3.2 J3.3 J3.7 J3.8 J3.9 J4.7 J4.8 J4.9 J5.2 J5.7 J5.8 J5.9 J6.3 J6.7 J6.8 J6.9 J7.3 J7.7 J7.8 J7.9 J8.2 J8.8 J8.9 J10.2 J10.7 J10.8 J10.9 U1.2 U1.3 U1.6 U1.7 U1.8 U1.9 U1.11 U1.12 U1.13 U1.14 U1.15 U1.16 U6.6 U6.8 U7.1 U7.2 U7.3 U7.4 U7.5 U7.10 U7.11 U7.12 U7.13 U7.14 U7.15 U7.16 U7.17 U7.21 U7.22 U7.23 U7.24 U7.25 U7.26 U7.27 U7.28 U7.29 U7.30 U7.31 U7.32 U7.33 U7.34 U7.35 U7.36 U7.37 U7.38 U7.39 U9.1 U9.2 U9.3 U9.6 U9.7 U9.8 U9.9 U9.10 U9.11 U9.15 U9.16 U9.17 U9.18 U10.3 U11.2 U11.3 U11.4 U11.5 U11.6 U11.11 U11.12 U11.13 U11.14 U11.15 U11.16 U11.20 U11.21 U11.22 U11.23 U11.24 U11.25 U11.26 U11.27 U11.28 U12.1 U12.2 U12.3 U12.4 U12.5 U12.14 U12.15 U12.16 U12.17 U12.18 U12.19 U12.20 U12.21 U12.22 U12.23 U12.24 U12.25 U12.26 U12.27 U12.28 U12.29 U12.30 U12.31 U12.32 U12.33 U12.34 U12.35 U12.36 U12.37 U12.38 U12.39 U12.40 U17.2 U17.3 U17.5 U18.2 U18.3 U18.4 U18.5 U18.6 U18.7 U18.9 U18.10 U18.11 U18.12 U18.13 U18.14 U18.15 U18.16 U18.17 U18.18 U18.21 U18.22 U18.23 U18.24 U18.25 U18.26

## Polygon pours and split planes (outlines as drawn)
N00020 on Top Layer "Top Layer-N00020" (hatched 90Degree grid 0.508 track 0.3, remove dead copper, pour order 0): 199.176,46.656 221.876,46.656 221.876,71.756 199.176,71.756
N00056 on Top Layer "Top Layer-N00056" (hatched 90Degree grid 0.508 track 0.3, remove dead copper, pour order 2): 115.876,53.036 137.676,53.036 137.676,78.236 115.876,78.236
N00047 on Top Layer "Top Layer-N00047 1" (hatched 90Degree grid 0.508 track 0.508, remove dead copper, pour order 4): -32,-87.3
GND on Top Layer "Top Layer-GND" (hatched 90Degree grid 0.508 track 0.3, remove dead copper, pour order 6): 65.7,83.4 114.3,83.4 114.3,7.3 65.6,7.3 65.6,83.3
N00002 on Top Layer "Top Layer-N00002" (hatched 90Degree grid 0.508 track 0.3, remove dead copper, pour order 8): 139.7,78.372 161.2,78.372 161.2,11.672 139.9,11.672 139.9,78.372
N00133 on Top Layer "Top Layer-N00133" (hatched 90Degree grid 0.508 track 0.3, remove dead copper, pour order 10): 0.8,83.488 64.012,83.488 64.012,0.684 0.5,0.684 0.5,83.488
N00047 on Top Layer "Top Layer-N00047" (hatched 90Degree grid 0.5 track 0.3, remove dead copper, pour order 12): 115.4,50 138.3,50 138.3,8 115.4,8
N00155 on Top Layer "Top Layer-N00155" (hatched 90Degree grid 0.5 track 0.3, remove dead copper, pour order 14): 163.1,83.499 197.3,83.499 197.3,0.999 163.1,0.999 163.1,83.499
N00051 on Top Layer "Top Layer-N00051" (hatched 90Degree grid 0.5 track 0.3, remove dead copper, pour order 16): 198.6,39.9 222,39.9 222,6.8 198.8,6.8 198.8,39.9
N00076 on Bottom Layer "Bottom Layer-N00076 1" (hatched 90Degree grid 0.508 track 0.25, remove dead copper, pour order 18): 183.8,85.6
N00004 on Bottom Layer "Bottom Layer-N00004" (hatched 90Degree grid 0.508 track 0.3, remove dead copper, pour order 20): 199.276,72.756 221.676,72.756 221.676,47.156 199.42,47.156 199.42,72.856
N00055 on Bottom Layer "Bottom Layer-N00055" (hatched 90Degree grid 0.508 track 0.3, remove dead copper, pour order 22): 115.876,78.136 137.676,78.136 137.676,53.136 115.976,53.136 115.976,78.236
N00046 on Bottom Layer "Bottom Layer-N00046 1" (hatched 90Degree grid 0.508 track 0.508, remove dead copper, pour order 24): -32,-87.3
GND on Bottom Layer "Bottom Layer-GND 1" (hatched 90Degree grid 0.508 track 0.508, remove dead copper, pour order 26): -32,-87.3
GND on Bottom Layer "Bottom Layer-GND" (hatched 90Degree grid 0.508 track 0.508, remove dead copper, pour order 28): 62.488,83.896
N00001 on Bottom Layer "Bottom Layer-N00001" (hatched 90Degree grid 0.508 track 0.3, remove dead copper, pour order 30): 139.82,78.512 161.12,78.512 161.12,11.812 139.82,11.812
N00079 on Bottom Layer "Bottom Layer-N00079" (hatched 90Degree grid 0.508 track 0.3, remove dead copper, pour order 32): 0.5,83.6 64.4,83.6 64.4,0.5 0.5,0.5
N00046 on Bottom Layer "Bottom Layer-N00046" (hatched 90Degree grid 0.5 track 0.3, remove dead copper, pour order 34): 115.6,50 138.3,50 138.3,8 115.4,8 115.4,50
N00076 on Bottom Layer "Bottom Layer-N00076" (hatched 90Degree grid 0.5 track 0.3, remove dead copper, pour order 36): 163,83.4 197.4,83.4 197.4,0.7 162.9,0.7 162.9,83.4
N00052 on Bottom Layer "Bottom Layer-N00052" (hatched 90Degree grid 0.5 track 0.3, remove dead copper, pour order 38): 198.6,39.9 222.1,39.9 222.1,6.5 198.6,6.5

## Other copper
Top Layer:
  text "PonyProg SI v2.2" at 78,12.9 h1.52
  text "by LancOS" at 81.6,9.7 h1.8

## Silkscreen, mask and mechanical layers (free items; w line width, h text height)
Top Overlay:
  text "1" at 16.3,80.1 h1.52
  text "10" at 46.3,80 h1.52
  text "10" at 193,79.2 h2
  text "1" at 164.3,78.9 h2
  text "89S" at 1.688,78.196 h1.52 r270
  text "AVR adapter" at 12.62,76.4 h1.52
  text "10" at 121.176,76.044 h1.52 r90
  text "10" at 202.356,73.904 h1.52 r90
  text "2323/Tiny12" at 19.5,73.228 h1.52 r270
  text "90S" at 1.836,69.792 h1.52 r270
  text "250x0" at 137.256,68.936 h1.52 r90
  text "PonyProg" at 134.476,66.136 h1.52 r90
  text "+" at 108.6,62.1 h1.52
  text "Ext" at 177.3,61.576 h1.52 r90
  text "-" at 108.6,59.2 h1.52
  text "Ext" at 78.236,56.7 h1.52 r270
  text "Bat" at 177.2,55.28 h1.52 r90
  text "10" at 143,55.064 h1.52 r90
  text "Pwr" at 80,54.94 h1.52 r270
  text "1" at 121.508,54.436 h1.52 r90
  text "Int" at 78.164,50.776 h1.52 r270
  text "1" at 202.456,45.244 h1.52 r90
  text "10" at 120.976,42.236 h1.52 r90
  text "PonyProg 2000" at 200.628,41.556 h1.52
  text "PonyProg  2000" at 1.86,36.6 h1.52 r270
  text "10" at 204.6,36.2 h1.52 r90
  text "93Cx6" at 132.876,33.844 h1.52 r90
  text "- +" at 195.236,28.2 h1.52 r180
  text "1" at 143.3,25.964 h1.52 r90
  text "1" at 121.008,20.536 h1.52 r90
  text "93Cx6X" at 131.6,20.3 h1.52 r90
  text "10" at 99.6,16.5 h1.52
  text "1" at 78.1,16.2 h1.52
  text "AT89Sxx" at 24,15.824 h1.52
  text "8535/4434" at 46.4,15.824 h1.52
  text "8515/4414" at 23.88,14 h1.52
  text "1" at 204.7,12.6 h1.52 r90
  text "93Cx6" at 137.5,11.9 h1.52 r90
  text "PonyProg" at 164,10.3 h1.52
  text "NVM3060" at 206.6,9.9 h1.52
  text "2000" at 166.4,7.5 h1.52
  text "2000" at 121.2,1.9 h1.52 r90
  text "PonyProg" at 118.376,1.62 h1.52 r90
  text "I2C Bus adapter" at 141.8,1.6 h1.52 r90
  text "PonyProg 2000" at 144.3,1.5 h1.52 r90
Bottom Overlay:
  lines w0.4: 35.7,39.7 40.7,39.7
Mechanical 1:
  lines w0.4: 64.8,0.2 64.8,84 ; 114.9,0.2 114.9,84 ; 139,0.1 139,84 ; 162.4,0.1 162.4,84 ; 198,0 198,84 ; 0,0 0,84 222.8,84 222.8,0 0,0
Mechanical 4:
  lines w0.254: 120.913,-89.739 ccw(c123.479,-89.739) 123.434,-92.304 ; 123.453,-92.305 230.133,-92.305 ccw(c230.133,-89.765) 232.673,-89.765
  lines w0.635: 122.183,-89.765 ccw(c123.453,-89.765) 123.431,-91.035 ; 123.453,-91.035 165.998,-91.035 ; 166.028,-91.035 ccw(c166.049,-89.816) 167.268,-89.773 ; 168.538,-89.765 ccw(c169.808,-89.765) 169.786,-91.035 ; 169.808,-91.035 212.353,-91.035 ; 212.383,-91.035 ccw(c212.404,-89.816) 213.623,-89.773 ; 214.893,-89.79 ccw(c216.138,-89.79) 216.16,-91.035 ; 216.163,-91.035 230.133,-91.035 ccw(c230.133,-89.765) 231.403,-89.765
